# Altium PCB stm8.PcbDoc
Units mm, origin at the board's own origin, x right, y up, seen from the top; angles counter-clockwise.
Board outline 53.34 x 78.1 mm, 2 copper layers (Top Layer, Bottom Layer); 23 components, 44 nets, 143 pads, 65 vias.
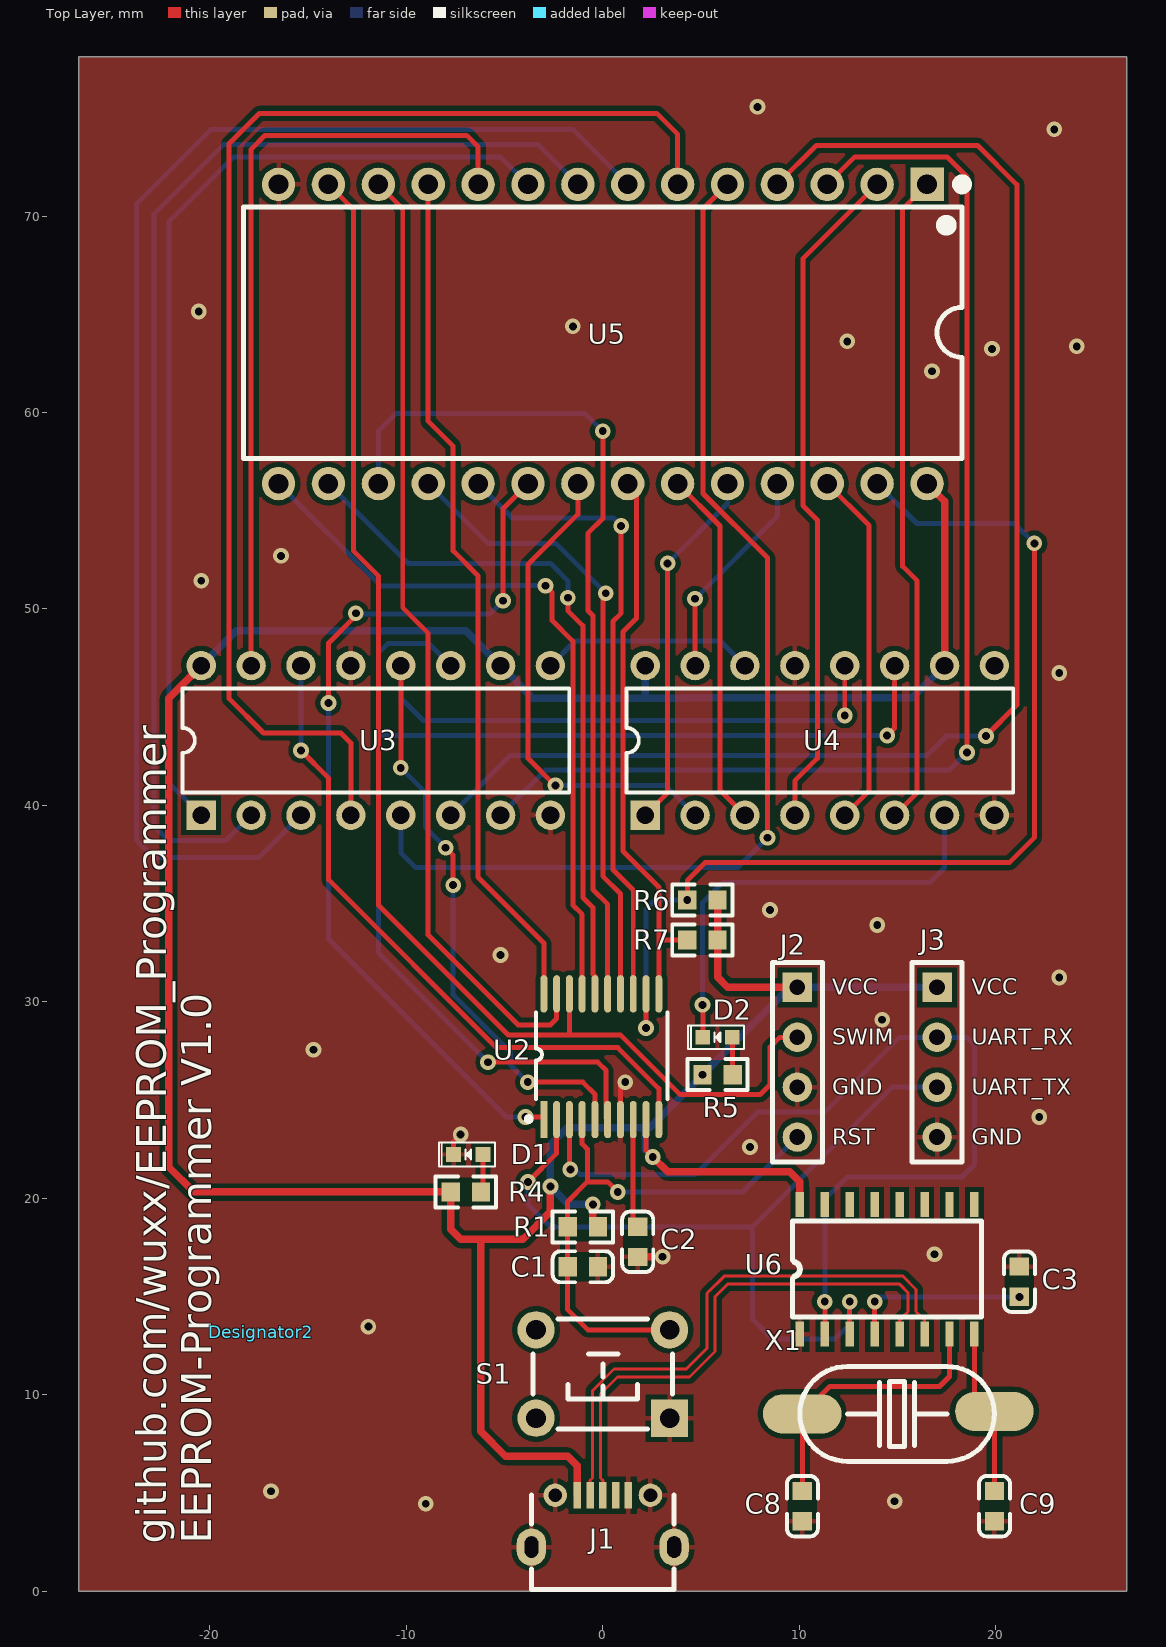
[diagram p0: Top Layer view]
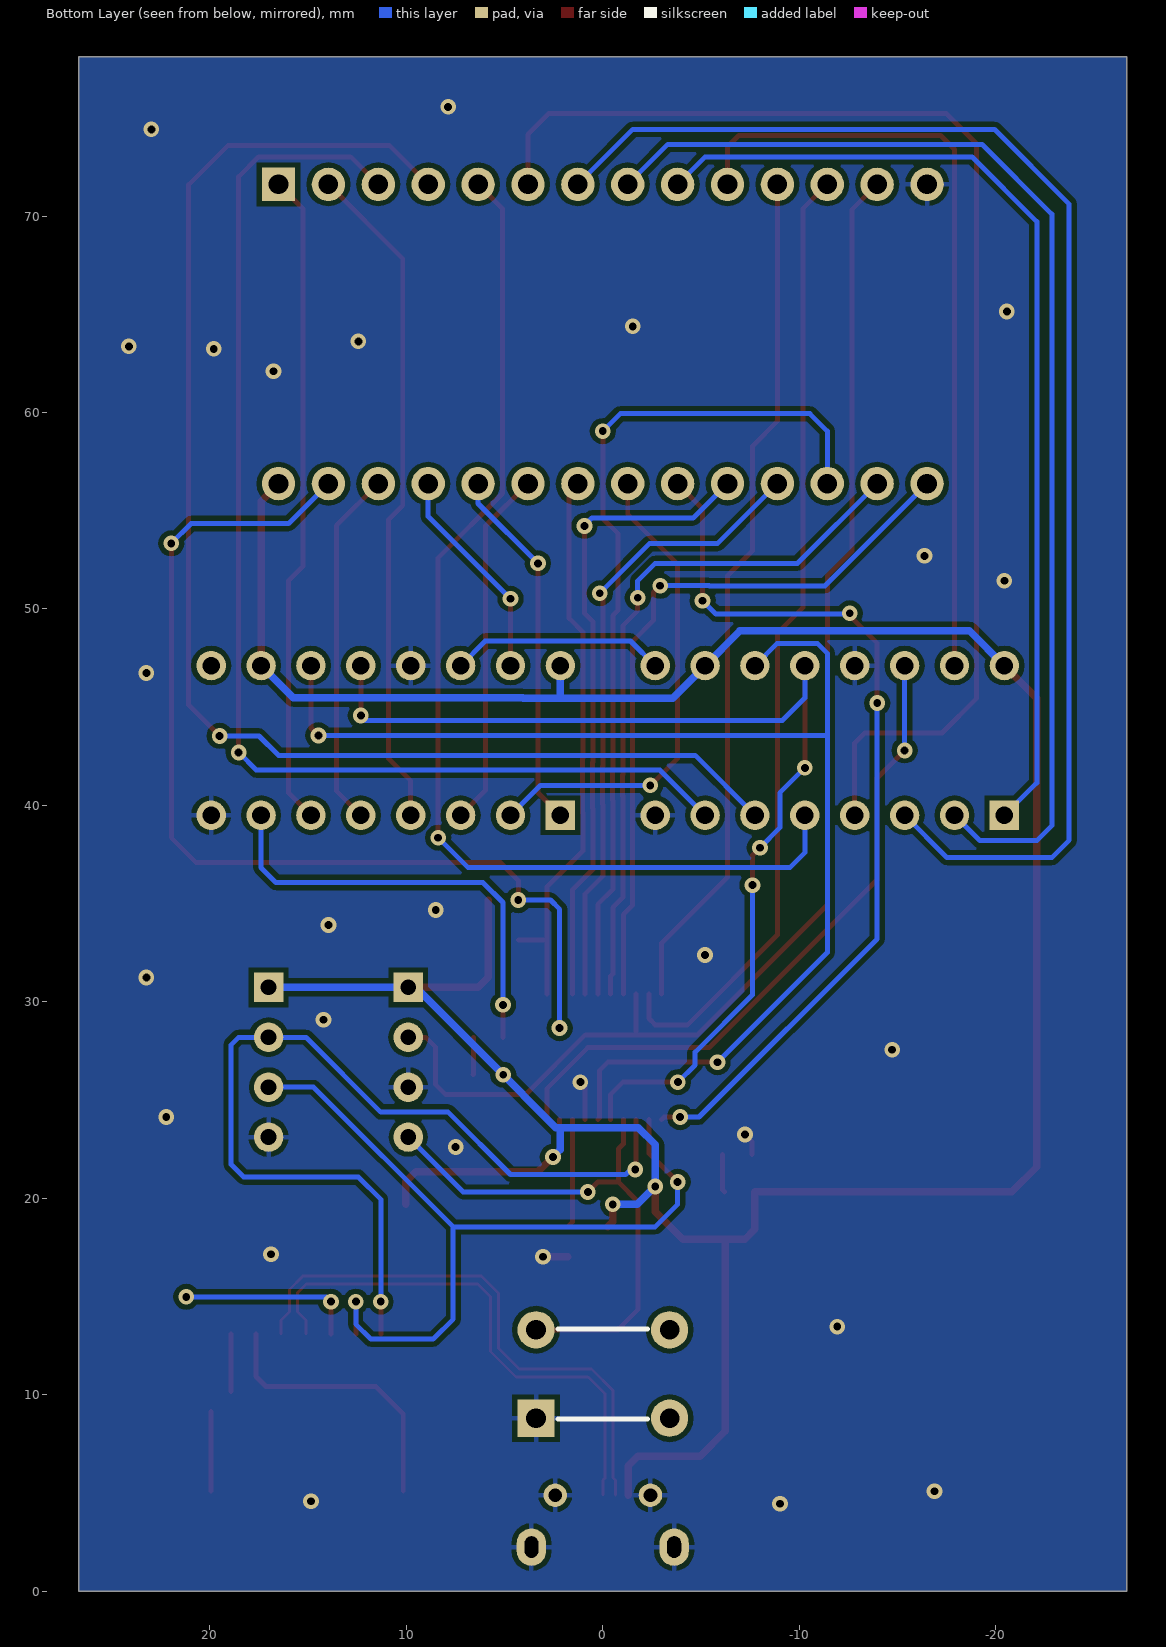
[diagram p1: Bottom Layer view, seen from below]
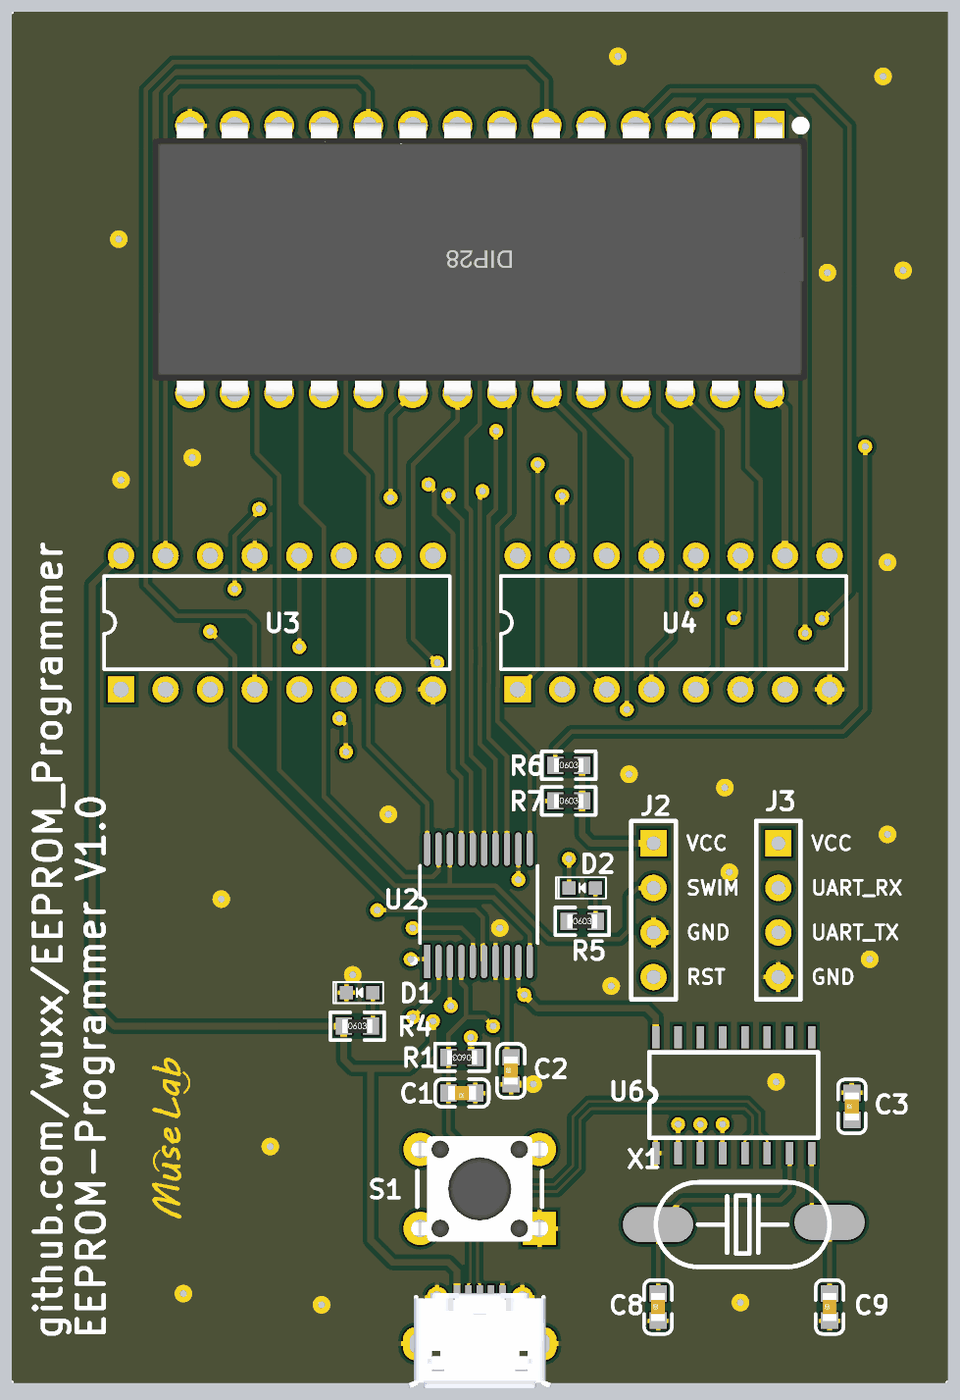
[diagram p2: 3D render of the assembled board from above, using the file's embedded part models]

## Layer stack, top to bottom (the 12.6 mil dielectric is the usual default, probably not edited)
Top Solder: solder mask 0.0102, Solder Resist, Dk 3.5
Top Layer: signal copper 0.0356
Dielectric 1: dielectric 0.32, FR-4, Dk 4.8
Bottom Layer: signal copper 0.0356
Bottom Solder: solder mask 0.0102, Solder Resist, Dk 3.5

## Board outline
-26.67,0 26.67,0 26.67,78.105 -26.67,78.105

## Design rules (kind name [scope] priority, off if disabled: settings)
Clearance [All] p1: gap=0.254 ignorepadtopadclearanceinfootprint=FALSE except(0: Arc-Hole Track-Hole SMDPad-Hole THPad-Hole Via-Hole Fill-Hole Poly-Hole Region-Hole Text-Hole)
DiffPairsRouting [All] p1: maxlimit=0.254 minlimit=0.254 mostfreqgap=0.254 toplayer_minwidth=0.152 toplayer_maxwidth=0.381 toplayer_prefwidth=0.381 bottomlayer_minwidth=0.152 bottomlayer_maxwidth=0.381 bottomlayer_prefwidth=0.381 maxuncoupledlength=12.7
PolygonConnect [All] p1: thpad.connectstyle=Relief thpad.reliefconductorwidth=0.254 thpad.reliefentries=4 thpad.polygonreliefangle="90 Angle" thpad.airgapwidth=0.254 smdpad.connectstyle=Relief smdpad.reliefconductorwidth=0.254 smdpad.reliefentries=4 smdpad.polygonreliefangle="90 Angle" smdpad.airgapwidth=0.254 via.connectstyle=Direct via.reliefconductorwidth=0.254 via.reliefentries=4 via.polygonreliefangle="90 Angle" via.airgapwidth=0.254
RoutingVias [All] p1: holewidth=0.4 width=0.8 viastyle="Through Hole" minholewidth=0.4 minwidth=0.8 maxholewidth=0.4 maxwidth=0.8
SolderMaskExpansion [All] p1: expansion=0.102
Width [All] p1: maxlimit=2.54 minlimit=0.152 preferedwidth=0.254
29 further rules are at their usual default settings.

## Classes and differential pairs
differential pair USB: +USB_P -USB_N

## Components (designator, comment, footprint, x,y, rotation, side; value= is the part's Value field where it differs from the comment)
C1 "Cap" 0603_C -0.254,16.51 r180 top value=100nF
C2 "Cap" 0603_C 1.778,17.018 r90 top value=1uF
C3 "0.1uF" 0603_C 21.209,14.986 r90 top value=1uF
C8 "20pF" 0603_C 10.16,3.556 r90 top value=1uF
C9 "20pF" 0603_C 19.939,3.556 r90 top value=1uF
D1 "LED0" 0603_LED -6.85,22.225 r180 top
D2 "LED0" 0603_LED 5.842,28.194 r180 top
Designator2 "Comment" LOGO -17.399,13.208 r90 top
J1 "Micro USB B" USB_MICRO_5S_B 0,3.556 r180 top
J2 "Header 4" HEADER_4x1 9.906,30.734 r270 top
J3 "Header 4" HEADER_4x1 17.018,30.734 r270 top
R1 "Res2" 0603_R -0.254,18.542 r180 top value=1K
R4 "Res2" 0603_R -7.739,20.32 r0 top value=1K
R5 "Res2" 0603_R 5.08,26.289 r0 top value=1K
R6 "Res2" 0603_R 4.31,35.179 r0 top value=4.7K
R7 "Res2" 0603_R 4.31,33.147 r0 top value=4.7K
S1 "SW-PB" "TSW DIP-6*6*6" 0,11.049 r180 top
U2 "STM8S103F3P6" TSSOP20 -3,24.003 r90 top locked
U3 "SN74HC595N" N016 -11.557,43.307 r0 top locked
U4 "SN74HC595N" N016 11.049,43.307 r0 top locked
U5 "AT28C256" DIP28-600 0,64 r270 top locked
U6 "CH340G" CH340G 10.033,13.081 r90 top locked
X1 "XTAL" 49SMD 14.986,9.017 r0 top value=12MHz

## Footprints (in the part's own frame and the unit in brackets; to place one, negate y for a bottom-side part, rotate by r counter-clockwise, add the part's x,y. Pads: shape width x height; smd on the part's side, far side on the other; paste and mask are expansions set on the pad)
49SMD [mm]
  oval 4x2 smd: 1(-4.826,0) 2(4.953,0.127)
  silkscreen extent -4.95,-2.41 4.95,2.41
0603_C [mm]
  rect 0.93x0.98 smd: 1(-0.008,0) 2(1.532,0)
  silkscreen extent -0.77,-0.79 2.3,0.79, body extent -0.04,-0.4 1.56,0.4, height 0.3
0603_LED [mm]
  rect 0.75x0.75 smd: 1(-0.75,0) 2(0.75,0)
  silkscreen extent -1.35,-0.6 1.5,0.6
0603_R [mm]
  rect 0.93x0.98 smd: 1(-0.008,0) 2(1.532,0)
  silkscreen extent -0.77,-0.79 2.3,0.79, body extent -0.09,-0.4 1.61,0.4, height 0.56
CH340G [mm]
  rect 1.27x0.43 smd: 1(0,0) 2(0,-1.27) 3(0,-2.54) 4(0,-3.81) 5(0,-5.08) 6(0,-6.35) 7(0,-7.62) 8(0,-8.89) 9(6.6,-8.89) 10(6.6,-7.62) 11(6.6,-6.35) 12(6.6,-5.08) 13(6.6,-3.81) 14(6.6,-2.54) 15(6.6,-1.27) 16(6.6,0)
  silkscreen extent 0.87,-9.25 5.75,0.38
DIP28-600 [mm] "37.3*15.3*4长宽高）"
  rect 1.7x1.7 hole 1: 1(-7.62,16.51)
  round 1.7 hole 1: 2(-7.62,13.97) 3(-7.62,11.43) 4(-7.62,8.89) 5(-7.62,6.35) 6(-7.62,3.81) 7(-7.62,1.27) 8(-7.62,-1.27) 9(-7.62,-3.81) 10(-7.62,-6.35) 11(-7.62,-8.89) 12(-7.62,-11.43) 13(-7.62,-13.97) 14(-7.62,-16.51) 15(7.62,-16.51) 16(7.62,-13.97) 17(7.62,-11.43) 18(7.62,-8.89) 19(7.62,-6.35) 20(7.62,-3.81) 21(7.62,-1.27) 22(7.62,1.27) 23(7.62,3.81) 24(7.62,6.35) 25(7.62,8.89) 26(7.62,11.43) 27(7.62,13.97) 28(7.62,16.51)
  silkscreen extent -7.87,-18.29 6.35,18.54, body extent -7.78,-18.65 7.78,18.65, height 4.7
HEADER_4x1 [mm]
  rect 1.5x1.5 hole 0.8: 1(0,0)
  round 1.5 hole 0.8: 2(2.54,0) 3(5.08,0) 4(7.62,0)
  silkscreen extent -1.27,-1.27 8.89,1.27
LOGO [mm]
N016 [mm] "DIP; 16 Leads; Row Spacing 7.62 mm; Pitch 2.54 mm"
  rect 1.5x1.5 hole 0.9: 1(-8.89,-3.81)
  round 1.5 hole 0.9: 2(-6.35,-3.81) 3(-3.81,-3.81) 4(-1.27,-3.81) 5(1.27,-3.81) 6(3.81,-3.81) 7(6.35,-3.81) 8(8.89,-3.81) 9(8.89,3.81) 10(6.35,3.81) 11(3.81,3.81) 12(1.27,3.81) 13(-1.27,3.81) 14(-3.81,3.81) 15(-6.35,3.81) 16(-8.89,3.81)
  silkscreen extent -9.85,-2.65 9.85,2.65
TSSOP20 [mm] "20-pin, 4.40 mm body, 0.65 mm pitch"
  rect 1.9x0.356 smd: 1(0,0)
  oval 1.9x0.356 smd: 2(0,-0.65) 3(0,-1.3) 4(0,-1.95) 5(0,-2.6) 6(0,-3.25) 7(0,-3.9) 8(0,-4.55) 9(0,-5.2) 10(0,-5.85) 11(6.4,-5.85) 12(6.4,-5.2) 13(6.4,-4.55) 14(6.4,-3.9) 15(6.4,-3.25) 16(6.4,-2.6) 17(6.4,-1.95) 18(6.4,-1.3) 19(6.4,-0.65) 20(6.4,0)
  silkscreen extent -0.1,-6.3 5.45,0.9
"TSW DIP-6*6*6" [mm] "6*6*6mm"
  rect 1.9x1.9 hole 1: 1(-3.4,2.25)
  round 1.9 hole 1: 2(-3.4,-2.25) 3(3.4,-2.25) 4(3.4,2.25)
  silkscreen extent -3.56,-2.79 3.56,2.79, body extent -4.11,-3 4.11,3, height 5.95
USB_MICRO_5S_B [mil]
  rect 15x54 smd: 1(51,-52) 2(25.5,-52) 3(0,-52) 4(-25.5,-52) 5(-51,-52)
  oval 59.06x74.8 hole 27.56 slot 43.31 at 90 deg: 6(-143,52) 7(143,52)
  round 47.24 hole 27.5: 8(95.5,-52) 9(-95.5,-52)
  silkscreen extent -143,-52 143,137, body extent -161,-61 161,152, height 105

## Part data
C1 C2: "Capacitor"
C3 C8 C9: library part CAP, "Capacitor"
D1 D2: "Typical INFRARED GaAs LED"
J2 J3: "Header, 4-Pin"
R1 R4 R5 R6 R7: "Resistor"
S1: "Switch"
U2: "ST 8-bit  Microcontroller"
U3 U4: "8-Bit Shift Register with 3-State Output Registers"
U5: "EEPROM 32Kx8 256k bit   The AT28C256 is a high-performance Electrically Erasable and Programmable Read Only Memory. Its 256K of memory is organized as 32,768 words by 8 bits."

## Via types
v1: diameter 0.8, hole 0.4, Top Layer to Bottom Layer, 65 vias

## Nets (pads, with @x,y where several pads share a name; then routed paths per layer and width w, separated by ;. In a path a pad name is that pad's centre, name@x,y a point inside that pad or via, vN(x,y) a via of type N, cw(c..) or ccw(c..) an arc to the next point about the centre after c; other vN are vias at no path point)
5V: J1.1 J2.1 J3.1 R1.1 R4.1 R5.1 R6.2 R7.2 U2.9 U3.10 U3.16 U4.10 U4.16 U5.28 U6.16 | length 170.1
  Top Layer w0.254: U2.9 2.2,22.438 v1(2.54,22.098) ; R5.1@5.072,26.17 v1(5.072,26.289)
  Top Layer w0.381: U3.16 -22.098,45.466 -22.098,21.59 -20.828,20.32 R4.1 -7.747,18.415 -7.239,17.907 -6.223,17.907 ; v1(-2.667,20.599) -2.667,19.304 -4.064,17.907 -6.223,17.907 ; J1.1 -1.295,6.375 -1.778,6.858 -4.953,6.858 -6.223,8.128 -6.223,17.907 ; v1(-0.508,19.685) -0.508,18.804 R1.1 ; v1(2.54,22.098) 3.302,21.336 9.525,21.336 10.033,20.828 U6.16 ; R6.2 R7.2 5.842,31.242 6.35,30.734 J2.1 ; U5.28 17.399,55.491 U4.10
  Bottom Layer w0.254: J2.1@9.517,30.734 J2.1
  Bottom Layer w0.381: U3.16 -18.669,48.895 -6.985,48.895 U3.10 -3.556,45.466 2.159,45.466 ; v1(-0.508,19.685) -1.753,19.685 v1(-2.667,20.599) -2.667,22.733 -1.803,23.597 2.159,23.597 ; U4.16 2.159,45.466 ; v1(2.54,22.098) 2.159,22.479 2.159,23.597 ; v1(5.072,26.289) J2.1@9.517,30.734 ; 5.74,26.949 2.388,23.597 2.159,23.597 ; J2.1 J3.1 ; U4.10 15.76,45.478 4.064,45.478 4.052,45.466 2.159,45.466
A15: D2.2 U4.7 | length 22.6
  Top Layer w0.254: v1(5.08,29.845) 5.092,29.833 D2.2
  Bottom Layer w0.254: v1(5.08,29.845) 5.083,29.848 5.083,35.055 6.096,36.068 16.637,36.068 17.399,36.83 U4.7
GND: C1.1 C2.1 C3.2 C8.1 C9.1 D1.2 J1.5 J1.6 J1.7 J1.8 J1.9 J2.3 J3.4 S1.1 U2.7 U3.8 U3.13 U4.8 U4.13 U5.14 U6.1 | length 4.4
  Top Layer w0.254: D1.2 -7.6,22.88 v1(-7.239,23.241) ; U2.7 0.9,25.665 v1(1.143,25.908)
  Top Layer w0.381: C2.1 3.04,17.01 v1(3.048,17.018)
  other v1: -9.017,4.445 14.859,4.572 -16.891,5.08 -11.938,13.462 16.891,17.145 7.493,22.606 22.225,24.13 -14.732,27.559 14.224,29.083 23.241,31.242 -5.207,32.385 13.97,33.909 8.509,34.671 23.241,46.736 -20.447,51.435 -16.383,52.705 16.764,62.103 19.812,63.246 24.13,63.373 12.446,63.627 -1.524,64.389 -20.574,65.151 22.987,74.422 7.874,75.565
NetC2_2: C2.2 U2.8 | length 5.5
  Top Layer w0.254: U2.8 1.55,18.778 C2.2
NetC3_1: C3.1 U6.4 | length 9.1
  Top Layer w0.254: U6.4 v1(13.843,14.732)
  Bottom Layer w0.254: v1(13.843,14.732) 14.089,14.978 v1(21.209,14.978)
NetC8_2: C8.2 U6.7 X1.1 | length 14.4
  Top Layer w0.254: C8.2 X1.1 11.557,10.414 17.145,10.414 17.653,10.922 U6.7
NetC9_2: C9.2 U6.8 X1.2 | length 7
  Top Layer w0.254: 18.923,10.16 U6.8 ; C9.2 X1.2
NetD1_1: D1.1 R4.2 | length 1.9
  Top Layer w0.254: R4.2 -6.1,20.427 D1.1
NetD2_1: D2.1 R5.2 | length 1.9
  Top Layer w0.254: D2.1 6.592,26.309 R5.2
NetU3_1: U3.1 U5.9 | length 51.1
  Bottom Layer w0.254: U3.1 -22.098,41.148 -22.098,69.723 -18.796,73.025 -5.215,73.025 U5.9
NetU3_2: U3.2 U5.8 | length 60.9
  Bottom Layer w0.254: U3.2 -19.202,38.202 -22.098,38.202 -22.86,38.964 -22.86,70.104 -19.304,73.66 -3.31,73.66 U5.8
NetU3_3: U3.3 U5.7 | length 69.8
  Bottom Layer w0.254: U3.3 -17.526,37.338 -22.86,37.338 -23.749,38.227 -23.749,70.612 -19.939,74.422 -1.532,74.422 U5.7
NetU3_4: U3.4 U5.6 | length 65.5
  Top Layer w0.254: U3.4 -12.827,43.18 -13.335,43.688 -17.272,43.688 -19.038,45.454 -19.038,73.672 -17.475,75.235 2.743,75.235 3.81,74.168 U5.6
NetU3_5: U3.5 U5.5 | length 56.7
  Top Layer w0.254: U5.5 5.105,70.375 5.105,55.88 8.382,52.603 v1(8.382,38.354)
  Bottom Layer w0.254: U3.5 -10.287,37.592 -9.525,36.83 6.858,36.83 v1(8.382,38.354)
NetU3_6: U3.6 U5.4 | length 71.5
  Top Layer w0.254: U5.4 10.879,73.609 19.075,73.609 21.082,71.603 21.082,45.11 v1(19.507,43.536)
  Bottom Layer w0.254: U3.6 -4.699,42.545 16.51,42.545 17.501,43.536 v1(19.507,43.536)
NetU3_7: U3.7 U5.3 | length 62.5
  Top Layer w0.254: U5.3 12.835,73.025 17.526,73.025 18.542,72.009 v1(18.542,42.697)
  Bottom Layer w0.254: U3.7 -2.902,41.802 17.647,41.802 v1(18.542,42.697)
NetU3_9: U3.9 U4.14 | length 10.9
  Bottom Layer w0.254: U3.9 -1.414,48.37 5.986,48.37 U4.14
NetU3_15: U3.15 U5.10 | length 40.3
  Top Layer w0.254: U3.15 -17.907,73.406 -17.196,74.117 -6.934,74.117 -6.35,73.533 U5.10
NetU4_1: U4.1 U5.24 | length 18.6
  Top Layer w0.254: U4.1 3.302,40.64 v1(3.302,52.324)
  Bottom Layer w0.254: v1(3.302,52.324) 6.35,55.372 U5.24
NetU4_2: U4.2 U5.21 | length 24.7
  Top Layer w0.254: v1(-2.413,41.021) -2.438,41.021 -3.81,42.393 -3.81,52.281 -1.27,54.821 U5.21
  Bottom Layer w0.254: v1(-2.413,41.021) 3.175,41.021 U4.2
NetU4_3: U4.3 U5.23 | length 18.3
  Top Layer w0.254: U5.23 5.969,54.221 5.969,40.767 U4.3
NetU4_4: U4.4 U5.2 | length 34.5
  Top Layer w0.254: U4.4 9.779,41.25 10.922,42.393 10.922,54.534 10.185,55.27 10.185,67.835 U5.2
NetU4_5: U4.5 U5.26 | length 18.3
  Top Layer w0.254: U5.26 13.564,54.246 13.564,40.742 U4.5
NetU4_6: U4.6 U5.1 | length 33.4
  Top Layer w0.254: U4.6 16.002,40.64 16.002,51.435 15.265,52.172 15.265,70.375 U5.1
NetU4_15: U4.15 U5.25 | length 11
  Top Layer w0.254: U4.15 v1(4.699,50.521)
  Bottom Layer w0.254: v1(4.699,50.521) 8.89,54.712 U5.25
NRST: C1.2 J2.4 R1.2 S1.2 U2.4 | length 27.9
  Top Layer w0.254: U2.4 -1.05,22.767 -0.788,22.505 -0.788,20.834 ; v1(0.762,20.32) 0.248,20.834 -0.788,20.834 ; S1.2 -0.762,13.299 -1.786,14.323 C1.2 -1.786,17.501 R1.2 -1.786,19.836 -0.788,20.834
  Bottom Layer w0.254: v1(0.762,20.32) 7.112,20.32 J2.4
PA1: U2.5 U3.12 U4.12 | length 56.2
  Top Layer w0.254: v1(-10.287,41.91) U3.12 ; v1(-8.001,37.846) -7.62,37.465 v1(-7.62,35.941) ; v1(-3.822,25.908) -1.016,25.908 -0.4,25.292 U2.5 ; v1(12.319,44.577) U4.12
  Bottom Layer w0.254: v1(-10.287,41.91) -9.017,40.64 -9.017,38.862 v1(-8.001,37.846) ; U3.12 -10.287,45.466 -9.144,44.323 12.065,44.323 v1(12.319,44.577) ; v1(-7.62,35.941) -7.62,30.353 -4.699,27.432 -4.699,26.785 v1(-3.822,25.908)
PA2: U2.6 U3.11 U4.11 | length 66.4
  Top Layer w0.254: v1(-5.842,26.924) -0.254,26.924 0.159,26.511 0.159,24.094 U2.6 ; v1(14.478,43.561) 14.859,43.942 U4.11 U4.11@14.478,46.736
  Bottom Layer w0.254: -11.43,43.561 v1(14.478,43.561) ; U3.11 -8.878,48.248 -10.922,48.248 -11.43,47.74 -11.43,32.512 v1(-5.842,26.924)
PA3: U2.10 U3.14 | length 34.3
  Top Layer w0.254: v1(-15.367,42.799) -13.958,41.39 -13.958,36.208 -5.41,27.661 0.767,27.661 2.85,25.578 U2.10
  Bottom Layer w0.254: v1(-15.367,42.799) U3.14
PB4: R6.1 U2.12 U5.27 | length 53.9
  Top Layer w0.254: v1(2.2,28.661) U2.12 ; v1(4.302,35.179) 4.302,36.179 5.207,37.084 20.701,37.084 21.971,38.354 v1(21.971,53.34)
  Bottom Layer w0.254: v1(2.2,28.661) 2.2,34.712 2.667,35.179 v1(4.302,35.179) ; U5.27 15.994,54.356 20.955,54.356 v1(21.971,53.34)
PB5: R7.1 U2.11 U5.22 | length 28.7
  Top Layer w0.254: U5.22 1.714,55.936 1.714,49.524 1.016,48.825 1.016,42.416 1.035,42.397 1.035,40.412 1.028,40.405 1.028,39.638 1.016,39.626 1.016,37.675 2.85,35.841 2.85,33.782 U2.11 ; 2.85,33.147 R7.1
PC3: U2.13 U5.19 | length 32.6
  Top Layer w0.254: v1(0.933,54.229) 0.933,49.788 0.508,49.363 0.508,42.205 0.527,42.186 0.527,40.622 0.52,40.615 0.52,39.849 0.508,39.837 0.508,36.736 1.55,35.693 U2.13
  Bottom Layer w0.254: U5.19 -4.605,54.635 0.559,54.635 0.933,54.261 v1(0.933,54.229)
PC4: U2.14 U5.18 | length 32.2
  Top Layer w0.254: v1(0.152,50.8) 0,50.648 0,41.995 0.019,41.976 0.019,40.833 0.012,40.826 0.012,40.059 0,40.047 0,36.398 0.9,35.498 U2.14
  Bottom Layer w0.254: U5.18 -5.85,53.34 -2.388,53.34 v1(0.152,50.8)
PC5: U2.15 U5.17 | length 44.2
  Top Layer w0.254: v1(0,59.055) 0,54.61 -0.762,53.848 -0.762,49.919 -0.508,49.665 -0.508,41.784 -0.489,41.765 -0.489,41.043 -0.496,41.036 -0.496,40.27 -0.508,40.258 -0.508,35.72 0.25,34.961 U2.15
  Bottom Layer w0.254: U5.17 -11.43,59.055 -10.541,59.944 -0.889,59.944 v1(0,59.055)
PC6: U2.16 U5.16 | length 35.9
  Top Layer w0.254: v1(-1.778,50.571) -1.778,49.911 -1.016,49.149 -1.016,41.574 -0.997,41.555 -0.997,41.253 -1.004,41.246 -1.004,40.48 -1.016,40.468 -1.016,35.306 -0.51,34.8 -0.51,31.416 -0.4,31.306 U2.16
  Bottom Layer w0.254: U5.16 -9.914,52.324 -2.667,52.324 -1.778,51.435 v1(-1.778,50.571)
PC7: U2.17 U5.15 | length 37.3
  Top Layer w0.254: v1(-2.921,51.181) -2.584,50.844 -2.584,49.422 -1.524,48.362 -1.524,41.364 -1.512,41.351 -1.512,40.691 -1.524,40.678 -1.524,34.925 -1.05,34.451 U2.17
  Bottom Layer w0.254: U5.15 -11.311,51.181 -5.423,51.181 -5.403,51.2 -2.94,51.2 v1(-2.921,51.181)
PD1: J2.2 U2.18 U5.13 | length 67.5
  Top Layer w0.254: U5.13 -12.7,70.35 -12.7,52.959 -11.43,51.689 -11.43,34.925 -4.826,28.321 -1.7,28.321 ; U2.18 -1.7,28.321 ; J2.2 9.017,28.194 8.509,27.686 8.509,25.781 8.001,25.273 3.937,25.273 0.889,28.321 -1.7,28.321
PD2: U2.19 U5.12 | length 49.1
  Top Layer w0.254: U5.12 -10.185,70.375 -10.185,50.063 -8.89,48.768 -8.89,33.401 -4.318,28.829 -2.667,28.829 -2.35,29.146 U2.19
PD3: U2.20 U5.11 | length 43.7
  Top Layer w0.254: U5.11 -8.89,59.563 -7.62,58.293 -7.62,52.959 -6.35,51.689 -6.35,36.345 -3,32.995 U2.20
PD4: U2.1 U5.20 | length 46.2
  Top Layer w0.254: v1(-13.97,45.212) -13.97,48.26 -12.573,49.657 v1(-12.573,49.784) ; v1(-5.08,50.419) -5.08,55.11 U5.20 ; v1(-3.937,24.13) -3.127,24.13 U2.1
  Bottom Layer w0.254: v1(-13.97,45.212) -13.97,33.198 -4.902,24.13 v1(-3.937,24.13) ; v1@-12.573,49.74 -5.759,49.74 v1(-5.08,50.419)
PD5: J3.3 U2.2 U6.3 | length 42.4
  Top Layer w0.254: v1(-3.81,20.828) -2.35,22.288 U2.2 ; U6.3 v1(12.573,14.732)
  Bottom Layer w0.254: v1(-3.81,20.828) -3.81,19.685 -2.667,18.542 7.62,18.542 ; v1(12.573,14.732) 12.573,13.589 11.811,12.827 8.636,12.827 7.62,13.843 7.62,18.542 ; J3.3 14.732,25.654 7.62,18.542
PD6: J3.2 U2.3 U6.2 | length 47.6
  Top Layer w0.254: U2.3 -1.7,21.512 v1(-1.651,21.463) ; U6.2 v1(11.303,14.732)
  Bottom Layer w0.254: v1(-1.651,21.463) -1.422,21.463 -1.168,21.209 4.699,21.209 7.874,24.384 11.303,24.384 15.113,28.194 J3.2 18.542,28.194 18.923,27.813 18.923,21.717 18.288,21.082 12.446,21.082 11.303,19.939 v1(11.303,14.732)
USB_N: J1.2 U6.6 | length 28.6
  Top Layer w0.152: J1.2 -0.648,5.639 -0.527,5.759 -0.527,10.201 0.575,11.303 4.251,11.303 5.309,12.36 5.309,15.154 6.182,16.027 15.281,16.027 15.951,15.358 15.951,14.224 16.383,13.792 U6.6
USB_P: J1.3 U6.5 | length 27.3
  Top Layer w0.152: J1.3 0,5.639 -0.121,5.759 -0.121,10.033 0.743,10.897 4.42,10.897 5.715,12.192 5.715,14.986 6.35,15.621 15.113,15.621 15.545,15.189 15.545,14.224 15.113,13.792 U6.5
pads on no net: J1.4 S1.3 S1.4 U4.9 U6.9 U6.10 U6.11 U6.12 U6.13 U6.14 U6.15

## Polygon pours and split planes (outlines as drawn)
GND on Top Layer "GND_L01_P000" (solid, remove dead copper, pour order 0): -26.67,78.105 26.67,78.105 26.67,0 -26.67,0
GND on Bottom Layer "GND_L02_P002" (solid, remove dead copper, pour order 2): -26.67,78.105 26.67,78.105 26.67,0 -26.67,0

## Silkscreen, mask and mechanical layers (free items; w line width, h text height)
Top Overlay:
  text "VCC" at 11.684,30.353 h0.81
  text "VCC" at 18.796,30.353 h0.81
  text "SWIM" at 11.684,27.813 h0.81
  text "UART_RX" at 18.796,27.813 h0.81
  text "GND" at 11.684,25.273 h0.81
  text "UART_TX" at 18.796,25.273 h0.81
  text "RST" at 11.684,22.733 h0.81
  text "GND" at 18.796,22.733 h0.81
  text "github.com/wuxx/EEPROM_Programmer / EEPROM-Programmer V1.0" at -19.939,2.413 h1.52 r90
Mechanical 1:
  the board outline again, w0.152

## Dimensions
-26.67,78.105 to -26.67,0 on Top Overlay
-26.67,0 to 26.67,0 on Top Overlay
